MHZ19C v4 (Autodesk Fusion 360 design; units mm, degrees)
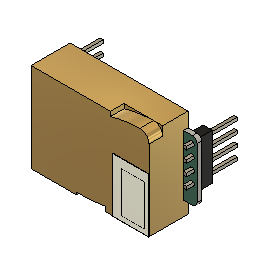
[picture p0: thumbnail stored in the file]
sketch "スケッチ1" plane through (0, 0, 0) normal (0, 1, 0) x axis (1, 0, 0)
sketch "スケッチ2" plane through (0, 0, 0) normal (0, 0, 1) x axis (1, 0, 0)
  line L1 (-1.725, 0) -> (0, 0)
  line L2 (-1.725, 1.57) -> (-1.725, 0)
  line L3 (0, 1.57) -> (-1.725, 1.57)
  line L4 (0, 0) -> (0, 1.57)
  line L5 (1.725, 1.57) -> (-1.725, 1.57)
  line L6 (1.725, -11.73) -> (1.725, 1.57)
  line L7 (-1.725, -11.73) -> (1.725, -11.73)
  line L8 (-1.725, 1.57) -> (-1.725, -11.73)
  line L9 (0, 0) -> (-1.725, 0)
  line L10 (0, -2.54) -> (0, 0)
  line L11 (-1.725, -2.54) -> (0, -2.54)
  line L12 (-1.725, 0) -> (-1.725, -2.54)
  line L13 (0, -2.54) -> (-1.725, -2.54)
  line L14 (0, -5.08) -> (0, -2.54)
  line L15 (-1.725, -5.08) -> (0, -5.08)
  line L16 (-1.725, -2.54) -> (-1.725, -5.08)
  line L17 (0, -5.08) -> (-1.725, -5.08)
  line L18 (0, -7.62) -> (0, -5.08)
  line L19 (-1.725, -7.62) -> (0, -7.62)
  line L20 (-1.725, -5.08) -> (-1.725, -7.62)
  line L21 (0, -7.62) -> (-1.725, -7.62)
  line L22 (0, -10.16) -> (0, -7.62)
  line L23 (-1.725, -10.16) -> (0, -10.16)
  line L24 (-1.725, -7.62) -> (-1.725, -10.16)
  line L25 (31.175, -5.08) -> (-1.725, -5.08)
  line L26 (31.175, 4.77) -> (31.175, -5.08)
  line L27 (-1.725, 4.77) -> (31.175, 4.77)
  line L28 (-1.725, -5.08) -> (-1.725, 4.77)
  line L29 (27.725, -5.08) -> (1.725, -5.08)
  line L30 (27.725, 4.77) -> (27.725, -5.08)
  line L31 (1.725, 4.77) -> (27.725, 4.77)
  line L32 (1.725, -5.08) -> (1.725, 4.77)
  line L33 (27.725, 4.77) -> (1.725, 4.77)
  line L34 (27.725, -14.93) -> (27.725, 4.77)
  line L35 (1.725, -14.93) -> (27.725, -14.93)
  line L36 (1.725, 4.77) -> (1.725, -14.93)
  line L37 (29.54, 0) -> (0, 0)
  line L38 (29.54, -7.62) -> (29.54, 0)
  line L39 (0, -7.62) -> (29.54, -7.62)
  line L40 (0, 0) -> (0, -7.62)
  line L41 (30.7064, 1.57) -> (-1.725, 1.57)
  line L42 (30.7064, -11.73) -> (30.7064, 1.57)
  line L43 (-1.725, -11.73) -> (30.7064, -11.73)
  line L44 (-1.725, 1.57) -> (-1.725, -11.73)
  line L45 (29.54, -2.54) -> (0, -2.54)
  line L46 (29.54, -5.08) -> (29.54, -2.54)
  line L47 (0, -5.08) -> (29.54, -5.08)
  line L48 (0, -2.54) -> (0, -5.08)
  line L49 (29.19, 0) -> (29.54, 0)
  line L50 (29.19, 0.35) -> (29.19, 0)
  line L51 (29.54, 0.35) -> (29.19, 0.35)
  line L52 (29.54, 0) -> (29.54, 0.35)
  line L53 (29.89, 0.35) -> (29.19, 0.35)
  line L54 (29.89, -0.35) -> (29.89, 0.35)
  line L55 (29.19, -0.35) -> (29.89, -0.35)
  line L56 (29.19, 0.35) -> (29.19, -0.35)
  line L57 (29.89, -2.19) -> (29.19, -2.19)
  line L58 (29.89, -2.89) -> (29.89, -2.19)
  line L59 (29.19, -2.19) -> (29.19, -2.89)
  line L60 (29.19, -2.89) -> (29.89, -2.89)
  line L61 (29.89, -4.73) -> (29.19, -4.73)
  line L62 (29.89, -5.43) -> (29.89, -4.73)
  line L63 (29.19, -5.43) -> (29.89, -5.43)
  line L64 (29.19, -4.73) -> (29.19, -5.43)
  line L65 (29.19, -7.97) -> (29.89, -7.97)
  line L66 (29.19, -7.27) -> (29.19, -7.97)
  line L67 (29.89, -7.97) -> (29.89, -7.27)
  line L68 (29.89, -7.27) -> (29.19, -7.27)
  line L69 (0.35, 0.35) -> (-0.35, 0.35)
  line L70 (0.35, -0.35) -> (0.35, 0.35)
  line L71 (-0.35, -0.35) -> (0.35, -0.35)
  line L72 (-0.35, 0.35) -> (-0.35, -0.35)
  line L73 (0.35, -2.19) -> (-0.35, -2.19)
  line L74 (0.35, -2.89) -> (0.35, -2.19)
  line L75 (-0.35, -2.19) -> (-0.35, -2.89)
  line L76 (-0.35, -2.89) -> (0.35, -2.89)
  line L77 (-0.35, -5.43) -> (0.35, -5.43)
  line L78 (-0.35, -4.73) -> (-0.35, -5.43)
  line L79 (0.35, -5.43) -> (0.35, -4.73)
  line L80 (0.35, -4.73) -> (-0.35, -4.73)
  line L81 (0.35, -7.27) -> (-0.35, -7.27)
  line L82 (0.35, -7.97) -> (0.35, -7.27)
  line L83 (-0.35, -7.27) -> (-0.35, -7.97)
  line L84 (-0.35, -7.97) -> (0.35, -7.97)
  line L85 (0.35, -9.81) -> (-0.35, -9.81)
  line L86 (0.35, -10.51) -> (0.35, -9.81)
  line L87 (-0.35, -10.51) -> (0.35, -10.51)
  line L88 (-0.35, -9.81) -> (-0.35, -10.51)
  line L89 (-0.725, 1.57) -> (-1.725, 1.57)
  line L90 (-0.725, 0.57) -> (-0.725, 1.57)
  line L91 (-1.725, 0.57) -> (-0.725, 0.57)
  line L92 (-1.725, 1.57) -> (-1.725, 0.57)
  line L93 (-0.725, -11.73) -> (-1.725, -11.73)
  line L94 (-0.725, -10.73) -> (-0.725, -11.73)
  line L95 (-1.725, -10.73) -> (-0.725, -10.73)
  line L96 (-1.725, -11.73) -> (-1.725, -10.73)
  line L97 (29.7064, -11.73) -> (30.7064, -11.73)
  line L98 (29.7064, -10.73) -> (29.7064, -11.73)
  line L99 (30.7064, -10.73) -> (29.7064, -10.73)
  line L100 (30.7064, -11.73) -> (30.7064, -10.73)
  line L101 (29.7064, 1.57) -> (30.7064, 1.57)
  line L102 (29.7064, 0.57) -> (29.7064, 1.57)
  line L103 (30.7064, 0.57) -> (29.7064, 0.57)
  line L104 (30.7064, 1.57) -> (30.7064, 0.57)
  line L105 (26.725, 3.77) -> (2.725, 3.77)
  line L106 (26.725, -13.93) -> (26.725, 3.77)
  line L107 (2.725, -13.93) -> (26.725, -13.93)
  line L108 (2.725, 3.77) -> (2.725, -13.93)
  line L109 (30.54, 0) -> (29.54, 0)
  line L110 (30.54, 1.27) -> (30.54, 0)
  line L111 (29.54, 1.27) -> (30.54, 1.27)
  line L112 (29.54, 0) -> (29.54, 1.27)
  line L113 (28.54, -7.62) -> (29.54, -7.62)
  line L114 (28.54, -8.89) -> (28.54, -7.62)
  line L115 (29.54, -8.89) -> (28.54, -8.89)
  line L116 (29.54, -7.62) -> (29.54, -8.89)
  line L117 (30.54, -8.89) -> (28.54, -8.89)
  line L118 (30.54, 1.27) -> (30.54, -8.89)
  line L119 (28.54, 1.27) -> (30.54, 1.27)
  line L120 (28.54, -8.89) -> (28.54, 1.27)
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  point P1 (0, 0)
  point P2 (0, 0)
  point P21 (0, 0)
  point P10 (0, -2.54)
  point P22 (0, -2.54)
  point P13 (0, -5.08)
  point P23 (0, -5.08)
  point P16 (0, -7.62)
  point P24 (0, -7.62)
  point P19 (0, -10.16)
  point P25 (0, -10.16)
  point P29 (1.725, -5.08)
  point P36 (0, 0)
  point P44 (29.54, -5.08)
  point P37 (29.54, 0)
  point P46 (29.54, 0)
  point P43 (29.54, -2.54)
  point P47 (29.54, -2.54)
  point P48 (29.54, -5.08)
  point P38 (29.54, -7.62)
  point P49 (29.54, -7.62)
  point P50 (29.54, 0)
  point P109 (29.54, 0)
  point P113 (29.54, -7.62)
  point P119 (0, 0)
  point P123 (0, -10.16)
  point P3 (-1.725, 0)
  point P5 (0, 1.57)
  point P4 (-1.725, 1.57)
  point P6 (1.725, 1.57)
  point P8 (-1.725, -11.73)
  point P9 (0, 0)
  point P11 (-1.725, -2.54)
  point P12 (0, -2.54)
  point P14 (-1.725, -5.08)
  point P15 (0, -5.08)
  point P17 (-1.725, -7.62)
  point P20 (-1.725, -10.16)
  point P26 (31.175, -5.08)
  point P28 (-1.725, 4.77)
  point P30 (27.725, -5.08)
  point P32 (1.725, 4.77)
  point P33 (27.725, 4.77)
  point P35 (1.725, -14.93)
  point P39 (0, -7.62)
  point P42 (-1.725, -11.73)
  point P51 (29.19, 0)
  point P53 (29.54, 0.35)
  point P52 (29.19, 0.35)
  point P54 (29.89, 0.35)
  point P56 (29.19, -0.35)
  point P57 (29.89, -2.19)
  point P59 (29.19, -2.19)
  point P58 (29.19, -2.89)
  point P63 (29.89, -4.73)
  point P65 (29.19, -4.73)
  point P64 (29.19, -5.43)
  point P62 (29.89, -7.27)
  point P68 (29.19, -7.27)
  point P67 (29.19, -7.97)
  point P71 (0.35, 0.35)
  point P78 (-0.35, 0.35)
  point P74 (-0.35, -0.35)
  point P70 (0.35, -2.19)
  point P82 (-0.35, -2.19)
  point P80 (-0.35, -2.89)
  point P83 (-0.35, -4.73)
  point P84 (0.35, -4.73)
  point P73 (-0.35, -5.43)
  point P77 (-0.35, -7.27)
  point P81 (0.35, -7.27)
  point P76 (-0.35, -7.97)
  point P86 (0.35, -9.81)
  point P87 (-0.35, -9.81)
  point P88 (-0.35, -10.51)
  point P89 (-0.725, 1.57)
  point P91 (-1.725, 0.57)
  point P93 (-0.725, -11.73)
  point P95 (-1.725, -10.73)
  point P41 (30.7064, -11.73)
  point P97 (29.7064, -11.73)
  point P99 (30.7064, -10.73)
  point P40 (30.7064, 1.57)
  point P101 (29.7064, 1.57)
  point P103 (30.7064, 0.57)
  point P110 (30.54, 0)
  point P112 (29.54, 1.27)
  point P114 (28.54, -7.62)
  point P116 (29.54, -8.89)
  point P120 (1, 0)
  point P122 (0, 1.27)
  point P124 (-1, -10.16)
  point P126 (0, -11.43)
  horizontal L1
  vertical L2
  horizontal L3
  vertical L4
  coincident P1 P2
  horizontal L5
  vertical L6
  horizontal L7
  vertical L8
  horizontal L9
  vertical L10
  horizontal L11
  vertical L12
  horizontal L13
  vertical L14
  horizontal L15
  vertical L16
  horizontal L17
  vertical L18
  horizontal L19
  vertical L20
  horizontal L21
  vertical L22
  horizontal L23
  vertical L24
  coincident P1 P21
  coincident P10 P22
  coincident P13 P23
  coincident P16 P24
  coincident P19 P25
  horizontal L25
  vertical L26
  horizontal L27
  vertical L28
  horizontal L29
  vertical L30
  horizontal L31
  vertical L32
  midpoint L6 P29
  horizontal L33
  vertical L34
  horizontal L35
  vertical L36
  horizontal L37
  vertical L38
  horizontal L39
  vertical L40
  coincident P21 P36
  horizontal L41
  vertical L42
  horizontal L43
  vertical L44
  horizontal L45
  vertical L46
  horizontal L47
  vertical L48
  coincident L25 P44
  coincident L38 P44
  coincident P37 P46
  coincident P43 P47
  coincident P44 P48
  coincident P38 P49
  horizontal L49
  vertical L50
  horizontal L51
  vertical L52
  coincident P46 P50
  horizontal L53
  vertical L54
  horizontal L55
  vertical L56
  horizontal L57
  vertical L58
  horizontal L60
  vertical L59
  horizontal L61
  vertical L62
  horizontal L63
  vertical L64
  horizontal L68
  vertical L67
  horizontal L65
  vertical L66
  horizontal L69
  vertical L70
  horizontal L71
  vertical L72
  horizontal L73
  vertical L74
  horizontal L76
  vertical L75
  horizontal L80
  vertical L79
  horizontal L77
  vertical L78
  horizontal L81
  vertical L82
  horizontal L84
  vertical L83
  horizontal L85
  vertical L86
  horizontal L87
  vertical L88
  horizontal L89
  vertical L90
  horizontal L91
  vertical L92
  horizontal L93
  vertical L94
  horizontal L95
  vertical L96
  horizontal L97
  vertical L98
  horizontal L99
  vertical L100
  horizontal L101
  vertical L102
  horizontal L103
  vertical L104
  horizontal L109
  vertical L110
  horizontal L111
  vertical L112
  coincident P46 P109
  horizontal L113
  vertical L114
  horizontal L115
  vertical L116
  coincident P49 P113
  horizontal L117
  vertical L118
  horizontal L119
  vertical L120
  coincident P1 P119
  coincident P25 P123
  dimension "d1" distance P2 P3 = 1.725
  dimension "d2" distance P2 P5 = 1.57
  dimension "d3" distance P4 P6 = 3.45
  dimension "d4" distance P4 P8 = 13.3
  dimension "d5" distance P3 P9 = 1.725
  dimension "d6" distance P3 P11 = 2.54
  dimension "d7" distance P11 P12 = 1.725
  dimension "d8" distance P11 P14 = 2.54
  dimension "d9" distance P14 P15 = 1.725
  dimension "d10" distance P14 P17 = 2.54
  dimension "d11" distance P17 P20 = 2.54
  dimension "d12" diameter = 1.1
  dimension "d13" diameter = 1.1
  dimension "d14" diameter = 1.1
  dimension "d15" diameter = 1.1
  dimension "d16" diameter = 1.1
  dimension "d17" distance P14 P26 = 32.9 (= "( 3.45 * 2 ) * 1 mm + 26 mm")
  dimension "d18" distance P14 P28 = 9.85
  dimension "d19" distance P29 P30 = 26
  dimension "d20" distance P29 P32 = 9.85
  dimension "d21" distance P32 P33 = 26
  dimension "d22" distance P32 P35 = 19.7
  dimension "d23" distance P36 P37 = 29.54
  dimension "d24" distance P36 P39 = 7.62 (= "( 2.54 * 3 ) * 1 mm")
  dimension "d25" distance P4 P42 = 13.3
  dimension "d26" diameter = 1.1
  dimension "d27" diameter = 1.1
  dimension "d28" diameter = 1.1
  dimension "d29" diameter = 1.1
  dimension "d30" distance P50 P51 = 0.35
  dimension "d31" distance P50 P53 = 0.35
  dimension "d32" distance P52 P54 = 0.7
  dimension "d33" distance P52 P56 = 0.7
  dimension "d34" distance P57 P59 = 0.7
  dimension "d35" distance P58 P59 = 0.7
  dimension "d36" distance P63 P65 = 0.7
  dimension "d37" distance P64 P65 = 0.7
  dimension "d38" distance P62 P68 = 0.7
  dimension "d39" distance P67 P68 = 0.7
  dimension "d40" distance P71 P78 = 0.7
  dimension "d41" distance P74 P78 = 0.7
  dimension "d42" distance P70 P82 = 0.7
  dimension "d43" distance P80 P82 = 0.7
  dimension "d44" distance P83 P84 = 0.7
  dimension "d45" distance P73 P83 = 0.7
  dimension "d46" distance P77 P81 = 0.7
  dimension "d47" distance P76 P77 = 0.7
  dimension "d48" distance P86 P87 = 0.7
  dimension "d49" distance P87 P88 = 0.7
  dimension "d50" distance P4 P89 = 1
  dimension "d51" distance P4 P91 = 1
  dimension "d52" distance P8 P93 = 1
  dimension "d53" distance P8 P95 = 1
  dimension "d54" distance P41 P97 = 1
  dimension "d55" distance P41 P99 = 1
  dimension "d56" distance P40 P101 = 1
  dimension "d57" distance P40 P103 = 1
  dimension "d58" = 1
  dimension "d61" distance P109 P110 = 1
  dimension "d62" distance P109 P112 = 1.27 (= "( 2.54 / 2 ) * 1 mm")
  dimension "d63" distance P113 P114 = 1
  dimension "d64" distance P113 P116 = 1.27 (= "( 2.54 / 2 ) * 1 mm")
  dimension "d65" distance P119 P120 = 1
  dimension "d66" distance P119 P122 = 1.27
  dimension "d67" distance P123 P124 = 1
  dimension "d68" distance P123 P126 = 1.27
extrude "押し出し1" new body sketch "スケッチ2" along normal blind 1 bodies "PCB"
extrude "押し出し2" new body sketch "スケッチ2" against normal blind 2.5 bodies "PinHeaderBody2", "PinHeaderBody1"
extrude "押し出し3" new body sketch "スケッチ2" against normal blind 8.7 bodies "PinHeader7", "PinHeader3", "PinHeader4", "PinHeader6", "PinHeader9", "PinHeader2", "PinHeader5", "PinHeader1"
extrude "押し出し4" add of existing geometry blind 2.5
extrude "押し出し5" new body sketch "スケッチ2" profile of L27 L30 L31 L32 L33 L34 L35 L36 L41 L43 L105 L108 L107 L106 along normal blind 8.6
sketch "スケッチ3" plane through (0, 1.57, 0) normal (0, -1, 0) x axis (1, 0, 0)
  line L1 (2.725, 0) -> (1.725, 0)
  line L2 (2.725, 8.6) -> (2.725, 0)
  line L3 (1.725, 8.6) -> (2.725, 8.6)
  line L4 (1.725, 0) -> (1.725, 8.6)
  line L5 (2.725, 8.6) -> (1.725, 8.6)
  line L6 (2.725, 1) -> (2.725, 8.6)
  line L7 (1.725, 1) -> (2.725, 1)
  line L8 (1.725, 8.6) -> (1.725, 1)
  line L9 (27.725, 8.6) -> (1.725, 8.6)
  line L10 (27.725, 1) -> (27.725, 8.6)
  line L11 (1.725, 1) -> (27.725, 1)
  line L12 (1.725, 8.6) -> (1.725, 1)
  line L13 (26.725, 8.6) -> (27.725, 8.6)
  line L14 (26.725, 1) -> (26.725, 8.6)
  line L15 (27.725, 1) -> (26.725, 1)
  line L16 (27.725, 8.6) -> (27.725, 1)
  line L17 (27.725, 8.6) -> (1.725, 8.6)
  line L18 (27.725, 7.6) -> (27.725, 8.6)
  line L19 (1.725, 7.6) -> (27.725, 7.6)
  line L20 (1.725, 8.6) -> (1.725, 7.6)
  point P5 (1.725, 8.6)
  point P6 (1.725, 8.6)
  point P9 (1.725, 1)
  point P10 (27.725, 8.6)
  point P13 (26.725, 8.6)
  point P18 (1.725, 7.6)
  horizontal L5
  vertical L6
  horizontal L7
  vertical L8
  coincident P5 P6
  horizontal L9
  vertical L10
  horizontal L11
  vertical L12
  horizontal L13
  vertical L14
  horizontal L15
  vertical L16
  horizontal L17
  vertical L18
  horizontal L19
  vertical L20
  dimension "d77" distance P6 P9 = 7.6
  dimension "d78" distance P6 P10 = 26
  dimension "d79" distance P10 P13 = 1
  dimension "d80" distance P6 P18 = 1
extrude "押し出し6" new body sketch "スケッチ3" profile of L2 L3 L4 L5 L6 L7 L8 L9 L10 L11 L12 L13 L14 L15 L16 L17 L18 L19 L20 along normal blind 16
extrude "押し出し7" new body sketch "スケッチ3" profile of L2 L3 L4 L5 L6 L7 L8 L9 L10 L11 L12 L13 L14 L15 L16 L17 L18 L19 L20 against normal blind 3 bodies "case"
combine "結合"
sketch "スケッチ4" plane through (0, 0, 8.6) normal (0, 0, 1) x axis (1, 0, 0)
  line L1 (27.725, 4.77) -> (27.725, -14.93)
  line L2 (1.725, 4.77) -> (27.725, 4.77)
  line L3 (1.725, -14.93) -> (1.725, 4.77)
  line L4 (27.725, -14.93) -> (1.725, -14.93)
  line L5 (19.225, 4.77) -> (27.725, 4.77)
  line L6 (19.225, 2.77) -> (19.225, 4.77)
  line L7 (27.725, 2.77) -> (19.225, 2.77)
  line L8 (27.725, 4.77) -> (27.725, 2.77)
  line L9 (25.725, 4.77) -> (27.725, 4.77)
  line L10 (25.725, 2.77) -> (25.725, 4.77)
  line L11 (27.725, 2.77) -> (25.725, 2.77)
  line L12 (27.725, 4.77) -> (27.725, 2.77)
  line L13 (22.475, 3.77) -> (22.3868, 4.0567)
  line L14 (11.725, -14.93) -> (1.725, -14.93)
  line L15 (11.725, -14.13) -> (11.725, -14.93)
  line L16 (1.725, -14.13) -> (11.725, -14.13)
  line L17 (1.725, -14.93) -> (1.725, -14.13)
  line L18 (18.125, -14.93) -> (11.725, -14.93)
  line L19 (18.125, -13.93) -> (18.125, -14.93)
  line L20 (11.725, -13.93) -> (18.125, -13.93)
  line L21 (11.725, -14.93) -> (11.725, -13.93)
  line L22 (10.725, -14.93) -> (11.725, -14.93)
  line L23 (10.725, -14.43) -> (10.725, -14.93)
  line L24 (11.725, -14.43) -> (10.725, -14.43)
  line L25 (11.725, -14.93) -> (11.725, -14.43)
  line L26 (18.125, -13.93) -> (11.725, -14.43)
  line L27 (18.1328, -14.0297) -> (11.7328, -14.5297)
  line L28 (14.9328, -14.2797) -> (14.925, -14.18)
  line L29 (10.725, -14.93) -> (10.725, -13.436)
  line L30 (19.125, -12.7656) -> (19.125, -14.93)
  line L31 (18.225, 1.0462) -> (18.225, 4.77)
  line L32 (25.725, 4.77) -> (19.225, 3.77)
  line L33 (25.6946, 4.9677) -> (19.1946, 3.9677)
  line L34 (22.4446, 4.4677) -> (22.475, 4.27)
  line L35 (21.725, -14.93) -> (27.725, -14.93)
  line L36 (21.725, -4.93) -> (21.725, -14.93)
  line L37 (27.725, -4.93) -> (21.725, -4.93)
  line L38 (27.725, -14.93) -> (27.725, -4.93)
  line L39 (19.725, -14.93) -> (27.725, -14.93)
  line L40 (19.725, -2.93) -> (19.725, -14.93)
  line L41 (27.725, -2.93) -> (19.725, -2.93)
  line L42 (27.725, -14.93) -> (27.725, -2.93)
  line L43 (21.725, -13.9302) -> (26.725, -13.9302)
  line L44 (21.725, -4.93) -> (21.725, -13.9302)
  line L45 (26.725, -4.93) -> (21.725, -4.93)
  line L46 (26.725, -13.9302) -> (26.725, -4.93)
  arc A1 centre (25.725, 2.77) radius 2 clockwise from (25.725, 4.77) to (27.725, 2.77)
  arc A2 centre (10.9167, 37.1262) radius 51.5625 clockwise from (18.125, -13.93) to (11.725, -14.43)
  arc A3 centre (10.9167, 37.1262) radius 50.5625 clockwise from (19.125, -12.7656) to (10.725, -13.436)
  arc A4 centre (25.725, 2.77) radius 1 clockwise from (25.725, 3.77) to (26.725, 2.77)
  circle C1 centre (11.725, -14.43) radius 1.0001
  circle C2 centre (18.125, -13.93) radius 1
  arc A5 centre (26.5701, -22.3481) radius 27.1313 clockwise from (19.225, 3.77) to (25.725, 4.77)
  arc A6 centre (26.5701, -22.3481) radius 26.1313 clockwise from (19.4957, 2.8073) to (25.7561, 3.7705)
  circle C3 centre (19.225, 3.77) radius 1
  point P3 (27.725, 4.77)
  point P6 (27.725, 4.77)
  point P11 (25.725, 2.77)
  point P13 (25.725, 2.77)
  point P5 (1.725, -14.93)
  point P16 (1.725, -14.93)
  point P28 (14.925, -14.18)
  point P29 (14.9328, -14.2797)
  point P25 (11.725, -14.43)
  point P41 (11.725, -14.43)
  point P21 (18.125, -13.93)
  point P42 (18.125, -13.93)
  point P43 (19.225, 3.77)
  point P46 (22.475, 4.27)
  point P47 (22.4446, 4.4677)
  point P52 (19.225, 3.77)
  point P2 (27.725, -14.93)
  point P53 (27.725, -14.93)
  point P7 (19.225, 4.77)
  point P9 (27.725, 2.77)
  point P10 (25.725, 4.77)
  point P17 (11.725, -14.93)
  point P19 (1.725, -14.13)
  point P20 (18.125, -14.93)
  point P22 (11.725, -13.93)
  point P23 (10.725, -14.93)
  point P54 (21.725, -14.93)
  point P56 (27.725, -4.93)
  point P57 (19.725, -14.93)
  point P59 (27.725, -2.93)
  horizontal L5
  vertical L6
  horizontal L7
  vertical L8
  coincident P3 P6
  horizontal L9
  vertical L10
  horizontal L11
  vertical L12
  coincident P11 P13
  horizontal L14
  vertical L15
  horizontal L16
  vertical L17
  coincident P5 P16
  horizontal L18
  vertical L19
  horizontal L20
  vertical L21
  horizontal L22
  vertical L23
  horizontal L24
  vertical L25
  midpoint L26 P28
  midpoint L27 P29
  perpendicular L27 L28
  coincident P29 A2
  concentric A2 A3
  parallel L21 L29
  parallel L19 L30
  parallel L6 L31
  coincident P25 P41
  coincident P21 P42
  tangent A3 C2
  midpoint L6 P43
  midpoint L32 P46
  midpoint L33 P47
  perpendicular L33 L34
  coincident P47 A5
  coincident P43 P52
  tangent L31 C3
  horizontal L35
  vertical L36
  horizontal L37
  vertical L38
  coincident P2 P53
  horizontal L39
  vertical L40
  horizontal L41
  vertical L42
  horizontal L43
  vertical L44
  horizontal L45
  vertical L46
  dimension "d85" distance P6 P7 = 8.5
  dimension "d86" distance P6 P9 = 2
  dimension "d87" distance P6 P10 = 2
  dimension "d89" distance P16 P17 = 10
  dimension "d90" distance P16 P19 = 0.8
  dimension "d91" distance P17 P20 = 6.4
  dimension "d92" distance P17 P22 = 1
  dimension "d93" distance P17 P23 = 1
  dimension "d94" distance P17 P25 = 0.5
  dimension "d95" = 0.1
  dimension "d105" = -1
  dimension "d106" = -0.2
  dimension "d107" = -1
  dimension "d112" distance P53 P54 = 6
  dimension "d113" distance P53 P56 = 10
  dimension "d114" distance P53 P57 = 8
  dimension "d115" distance P53 P59 = 12
extrude "押し出し8" cut sketch "スケッチ4" profile of L1 L2 L4 L5 L6 L8 L9 L12 A1 L15 L18 L19 L21 L25 L27 A2 C1 C2 L33 A5 C3 against normal blind 3
extrude "押し出し9" add sketch "スケッチ4" profile of L2 L4 L6 L7 L10 L11 A1 L14 L15 L16 L19 L20 L21 L22 L23 L24 L25 L29 A3 L30 L31 A4 C1 C2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 against normal blind 4
extrude "押し出し10" cut sketch "スケッチ4" profile of L36 L37 L43 L44 L45 L46 against normal blind 2
extrude "押し出し11" new body sketch "スケッチ4" profile of L1 L4 L35 L36 L37 L38 L39 L40 L41 L42 L43 L44 L45 L46 along normal blind 0.1 bodies "filter"
named bodies: "PCB", "PinHeaderBody2", "PinHeaderBody1", "PinHeader7", "PinHeader3", "PinHeader4", "PinHeader6", "PinHeader9", "PinHeader2", "PinHeader5", "PinHeader1", "PinHeader8", "case", "filter"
